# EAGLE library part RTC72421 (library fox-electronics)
Real Time Clock http://www.foxonline.com/72421.htm
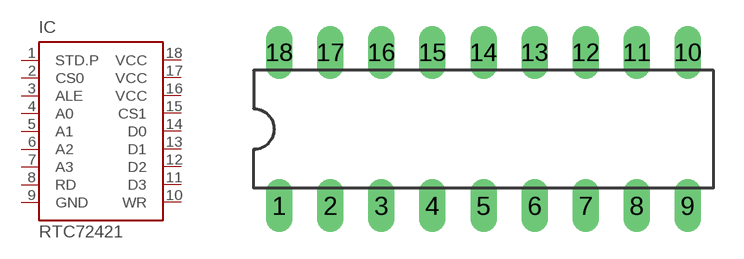
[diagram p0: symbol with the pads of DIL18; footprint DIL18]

Designator prefix IC

## RTC72421 (MPN: RTC72421B; OC_FARNELL: 1216228; OC_NEWARK: 01M8738)  [DIL18]
1  STD.P  in
2  CS0  in
3  ALE  in
4  A0  in
5  A1  in
6  A2  in
7  A3  in
8  RD  in
9  GND  pwr
10  WR  in
11  D3
12  D2
13  D1
14  D0
15  CS1  in
16  VCC  pwr
17  VCC  pwr
18  VCC  pwr

## Footprint DIL18 (pad centres in mm)
Dual In Line Package
drill 0.813 long: 1 -10.16,-3.81; 2 -7.62,-3.81; 3 -5.08,-3.81; 4 -2.54,-3.81; 5 0,-3.81; 6 2.54,-3.81; 7 5.08,-3.81; 8 7.62,-3.81; 9 10.16,-3.81; 10 10.16,3.81; 11 7.62,3.81; 12 5.08,3.81; 13 2.54,3.81; 14 0,3.81; 15 -2.54,3.81; 16 -5.08,3.81; 17 -7.62,3.81; 18 -10.16,3.81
